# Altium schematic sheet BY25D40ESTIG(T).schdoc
size 127 x 101 mm
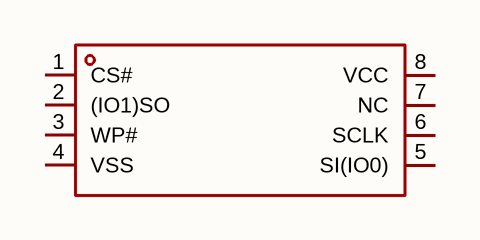
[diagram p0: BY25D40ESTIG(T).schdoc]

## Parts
U?  by25d40estig(t)  [SOP-8_L4.9-W3.9-P1.27-LS6.0-BL]  (value not drawn)

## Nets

Not connected (* = marked no-connect by the designer): U? 1(CS#) 2((IO1)SO) 3(WP#) 4(VSS) 5(SI(IO0)) 6(SCLK) 7(NC) 8(VCC)

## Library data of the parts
U? = by25d40estig(t): 接口类型:SPI;存储容量:4Mbit;时钟频率(fc):108MHz;; Manufacturer: BOYAMICRO(博雅); AddInBom: yes; ModelId: 75c24a7891ee4dd6bdac16a7163ff87e; ModelName: SOP-8_L4.9-W3.9-P1.27-LS6.0-BL-1; ModelTransform: 192.913,236.22,0,0,0,0,-0.393,2.749,0; Interface: SPI; Memory Size: 4Mbit; Clock Frequency: 108MHz; Voltage - Supply: 2.7V~3.6V; Standby Supply Current: 5uA; Program / Erase Cycles: 100000次; Page Programming Time (Tpp): 800us; Block Erase Time(tBE): 3s@(64KB); Data Retention - TDR (Year): 20年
